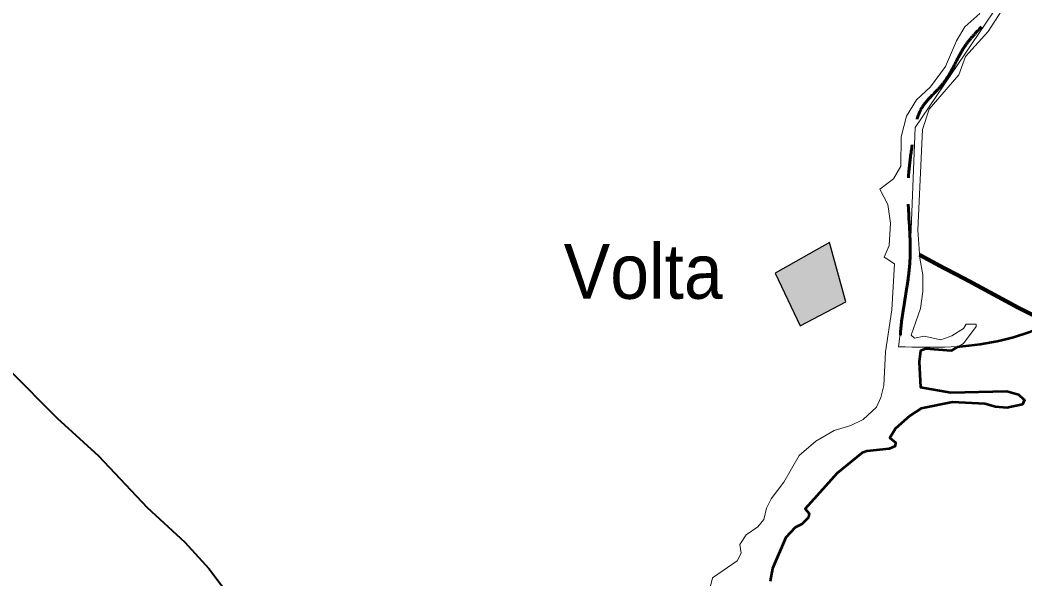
# Model space of a CAD drawing. Extents: x -1643653 to 4543381, y 1624270 to 13878484.
# Drawn here: x 584514 to 593659, y 8974247 to 8979336 of the extents above; entities that cross this region are included whole.
import ezdxf

# ---------------------------------------------------------------- set-up
doc = ezdxf.new("R2010")
doc.units = 0
doc.header["$LTSCALE"] = 200
doc.linetypes.add('LONG_DASH_SHORT_DASH', pattern=[9.9, 6, -1.2, 1.5, -1.2])
for name, color, linetype, lineweight in [('12', 7, 'Continuous', 25), ('21', 7, 'Continuous', 25), ('25', 7, 'Continuous', 13), ('58', 7, 'Continuous', 13), ('59', 7, 'Continuous', 53), ('60', 7, 'Continuous', 13), ('7', 7, 'LONG_DASH_SHORT_DASH', 60), ('9', 7, 'Continuous', 90)]:
    doc.layers.add(name, color=color, linetype=linetype, lineweight=lineweight)
doc.layers.add('41', color=7, linetype='Continuous')

msp = doc.modelspace()

# ---------------------------------------------------------------- hatches: boundary and pattern name
at = {"layer": '21'}
msp.add_hatch(color=256, dxfattribs=at).paths.add_polyline_path([(591387.2, 8977029.8), (591614.3, 8976550.1), (592028.7, 8976768.6), (591880.1, 8977309.9)])

# ---------------------------------------------------------------- linework, layer by layer
at = {"layer": '12', "lineweight": 40}
msp.add_lwpolyline([(584414.4, 8976152.1), (584852.4, 8975709.9), (585227.8, 8975368.9), (585671, 8974897.7), (586014.6, 8974582.2), (586230.8, 8974340.1), (586568.3, 8973894.4), (586761.1, 8973701.7), (586961.6, 8973436.3), (587301, 8972874.3), (587640.4, 8972251.7), (587788.5, 8972042.4), (588207.4, 8971376.7), (588263.1, 8971248.8), (588483.5, 8970850.8), (588695.4, 8970396.6), (588857.5, 8969895.4), (589190.3, 8968987.7)], dxfattribs=at)
at = {"layer": '21'}
msp.add_lwpolyline([(591387.2, 8977029.8), (591614.3, 8976550.1), (592028.7, 8976768.6), (591880.1, 8977309.9)], close=True, dxfattribs=at)
at = {"layer": '25'}
for points in [[(593541.1, 8979568.9), (593326.1, 8979230.3), (593118.1, 8979003.2), (593056.2, 8978837.1), (592788.7, 8978522.9), (592727, 8978339.3), (592684.6, 8977422.8), (592701.6, 8977167.9), (592731.3, 8977014.7), (592731.4, 8976862.7), (592710.1, 8976709.1), (592625.3, 8976466.7), (592653, 8976439.2), (592742.2, 8976458.1), (592894.9, 8976424.2), (592992.8, 8976460.4), (593098.8, 8976528.3), (593123.6, 8976567.4), (593214.3, 8976567.6), (593214.6, 8976559.7)], [(593541.1, 8979568.9), (593326.1, 8979230.3), (593118.1, 8979003.2), (593056.2, 8978837.1), (592788.7, 8978522.9), (592727, 8978339.3), (592684.6, 8977422.8), (592701.6, 8977167.9), (592731.3, 8977014.7), (592731.4, 8976862.7), (592710.1, 8976709.1), (592625.3, 8976466.7), (592653, 8976439.2), (592742.2, 8976458.1), (592894.9, 8976424.2), (592992.8, 8976460.4), (593098.8, 8976528.3), (593123.6, 8976567.4), (593214.3, 8976567.6), (593214.6, 8976559.7)], [(592340.2, 8977796.1), (592463.6, 8977889.9), (592529.4, 8978006.6), (592531.7, 8978272), (592582.8, 8978459.4), (592672, 8978608.1), (592799.5, 8978729.2), (592937.2, 8978913.6), (593037.2, 8979147.4), (593113.6, 8979274.7), (593249.5, 8979396.5)], [(592340.2, 8977796.1), (592463.6, 8977889.9), (592529.4, 8978006.6), (592531.7, 8978272), (592582.8, 8978459.4), (592672, 8978608.1), (592799.5, 8978729.2), (592937.2, 8978913.6), (593037.2, 8979147.4), (593113.6, 8979274.7), (593249.5, 8979396.5)], [(592403.5, 8977160.8), (592376.8, 8977178.1), (592423.3, 8977282.6), (592436.1, 8977486), (592410.8, 8977655.4), (592340.2, 8977796.1)], [(592403.5, 8977160.8), (592376.8, 8977178.1), (592423.3, 8977282.6), (592436.1, 8977486), (592410.8, 8977655.4), (592340.2, 8977796.1)], [(590792, 8974157.8), (590815.2, 8974257.2), (591040.4, 8974410.4), (591076.5, 8974482.4), (591063.8, 8974558.8), (591121.2, 8974648.3), (591227.2, 8974720.4), (591282.6, 8974788.8), (591308.2, 8974890.7), (591350.1, 8974974.6), (591465.3, 8975128.4), (591603.2, 8975370.3), (591756.1, 8975500), (591922, 8975597.8), (592075.7, 8975644.8), (592185.6, 8975697.8), (592308.6, 8975810.4), (592349.1, 8975899.9), (592374.4, 8976007.6), (592391.5, 8976313.7), (592449, 8976697.9), (592471.9, 8977116.8), (592403.5, 8977160.8)], [(590792, 8974157.8), (590815.2, 8974257.2), (591040.4, 8974410.4), (591076.5, 8974482.4), (591063.8, 8974558.8), (591121.2, 8974648.3), (591227.2, 8974720.4), (591282.6, 8974788.8), (591308.2, 8974890.7), (591350.1, 8974974.6), (591465.3, 8975128.4), (591603.2, 8975370.3), (591756.1, 8975500), (591922, 8975597.8), (592075.7, 8975644.8), (592185.6, 8975697.8), (592308.6, 8975810.4), (592349.1, 8975899.9), (592374.4, 8976007.6), (592391.5, 8976313.7), (592449, 8976697.9), (592471.9, 8977116.8), (592403.5, 8977160.8)], [(593214.6, 8976559.7), (593215.2, 8976544.7), (593099, 8976390.4), (592986.9, 8976322.5), (592758.7, 8976343.4), (592708.2, 8976324.4), (592695.2, 8976224.5), (592709.9, 8975991.5), (592983.9, 8975944.1), (593493.9, 8975956.8), (593602.1, 8975927.4), (593649.1, 8975881.7)], [(593214.6, 8976559.7), (593215.2, 8976544.7), (593099, 8976390.4), (592986.9, 8976322.5), (592758.7, 8976343.4), (592708.2, 8976324.4), (592695.2, 8976224.5), (592709.9, 8975991.5), (592983.9, 8975944.1), (593493.9, 8975956.8), (593602.1, 8975927.4), (593649.1, 8975881.7)], [(593649.1, 8975881.7), (593655, 8975876), (593638.1, 8975835.7), (593493.9, 8975806), (593392, 8975812.4), (593294, 8975840), (593001.4, 8975857), (592713.8, 8975797.2), (592610.3, 8975731.6), (592482.8, 8975616.5), (592429.9, 8975529.9), (592480.5, 8975487.5), (592478.3, 8975455.5), (592423.1, 8975432.1), (592219.4, 8975410.8), (592178.8, 8975393.7), (591951.5, 8975211), (591658.9, 8974884.4), (591696.9, 8974843.5), (591690.4, 8974805.5), (591629, 8974746.2), (591569.4, 8974716.2), (591482.2, 8974622.5), (591361.3, 8974342.6), (591339.9, 8974225.6)], [(593649.1, 8975881.7), (593655, 8975876), (593638.1, 8975835.7), (593493.9, 8975806), (593392, 8975812.4), (593294, 8975840), (593001.4, 8975857), (592713.8, 8975797.2), (592610.3, 8975731.6), (592482.8, 8975616.5), (592429.9, 8975529.9), (592480.5, 8975487.5), (592478.3, 8975455.5), (592423.1, 8975432.1), (592219.4, 8975410.8), (592178.8, 8975393.7), (591951.5, 8975211), (591658.9, 8974884.4), (591696.9, 8974843.5), (591690.4, 8974805.5), (591629, 8974746.2), (591569.4, 8974716.2), (591482.2, 8974622.5), (591361.3, 8974342.6), (591339.9, 8974225.6)]]:
    msp.add_lwpolyline(points, dxfattribs=at)
at = {"layer": '58'}
msp.add_line((592616.3, 8977200.9), (592510.1, 8976360.8), dxfattribs=at)
msp.add_lwpolyline([(601551, 8986031.1), (600446.9, 8986057.4), (600164.2, 8985987.1), (599721.5, 8985889.5), (599344, 8985609.2), (599037.7, 8985250.2), (598611, 8985091.4), (598158.8, 8984413.5), (597693.6, 8984012), (597255.2, 8983474), (597144.4, 8983071.7), (594862.5, 8981319.9), (594017.1, 8980976.9), (593562.9, 8979696.3), (592660, 8978358.3), (592616.3, 8977200.9)], dxfattribs=at)
msp.add_spline([(592510.1, 8976360.8), (593459.4, 8976419.7), (594161.8, 8976760.1), (594545.8, 8977114.6), (594814.3, 8977291.5), (596052.8, 8977846), (596780.5, 8978160.9), (597647.4, 8978322.7), (598691.5, 8978280.2), (599825, 8978301), (600207.2, 8978324.8), (600219.9, 8978324.8), (601221.6, 8978295.4)], degree=3, dxfattribs=at)
at = {"layer": '59'}
msp.add_line((593042.9, 8976356.4), (592986.9, 8976322.5), dxfattribs=at)
for points in [[(592986.9, 8976322.5), (592758.7, 8976343.4), (592708.2, 8976324.4), (592695.2, 8976224.5), (592709.9, 8975991.5), (592983.9, 8975944.1), (593493.9, 8975956.8), (593602.1, 8975927.4), (593649.1, 8975881.7)], [(593649.1, 8975881.7), (593655, 8975876), (593638.1, 8975835.7), (593493.9, 8975806), (593392, 8975812.4), (593294, 8975840), (593001.4, 8975857), (592713.8, 8975797.2), (592610.3, 8975731.6), (592482.8, 8975616.5), (592429.9, 8975529.9), (592480.5, 8975487.5), (592478.3, 8975455.5), (592423.1, 8975432.1), (592219.4, 8975410.8), (592178.8, 8975393.7), (591951.5, 8975211), (591658.9, 8974884.4), (591696.9, 8974843.5), (591690.4, 8974805.5), (591629, 8974746.2), (591569.4, 8974716.2), (591482.2, 8974622.5), (591361.3, 8974342.6), (591339.9, 8974225.6)]]:
    msp.add_lwpolyline(points, dxfattribs=at)
msp.add_spline([(601221.6, 8978295.4), (600219.9, 8978324.8), (600207.2, 8978324.8), (599825, 8978301), (598691.5, 8978280.2), (597647.4, 8978322.7), (596780.5, 8978160.9), (596052.8, 8977846), (594814.3, 8977291.5), (594545.8, 8977114.6), (594161.8, 8976760.1), (593459.4, 8976419.7), (593042.9, 8976356.4)], degree=3, dxfattribs=at)
at = {"layer": '60', "lineweight": 25}
msp.add_spline([(814781, 9009175.5), (814787.2, 9009173.4), (814796.9, 9009173.4), (814799.4, 9009172.4), (814805.1, 9009174.5), (814805.6, 9009176.5), (814811.7, 9009179.5), (814811.7, 9009179.5), (814801.5, 9009181), (814790.7, 9009181.5), (814784.1, 9009183.1), (814777.4, 9009185.1), (814778.4, 9009175.5)], degree=3, dxfattribs=at)
at = {"layer": '7'}
msp.add_spline([(592525.2, 8976466.9), (592528.1, 8976506.5), (592612.5, 8977139.6), (592595.6, 8977840.2), (592646.2, 8978279.2), (592713.7, 8978524), (592916.2, 8978760.3), (593118.7, 8979106.4), (593264.9, 8979274.8)], degree=3, dxfattribs=at)
at = {"layer": '9'}
msp.add_spline([(592698.5, 8977198.4), (599903.5, 8973292.7), (608459.2, 8968138.2), (612674.8, 8965332.6), (616842, 8962096.4), (620005, 8958671.2), (621134, 8957974.7), (621473.4, 8956805.3), (621586.2, 8956597.5)], degree=3, dxfattribs=at)

# ---------------------------------------------------------------- texts
at = {"layer": '41', "width": 0.95}
msp.add_text('Volta', height=500, dxfattribs=at).set_placement((589461.3, 8976797.6))

doc.saveas('drawing.dxf')
